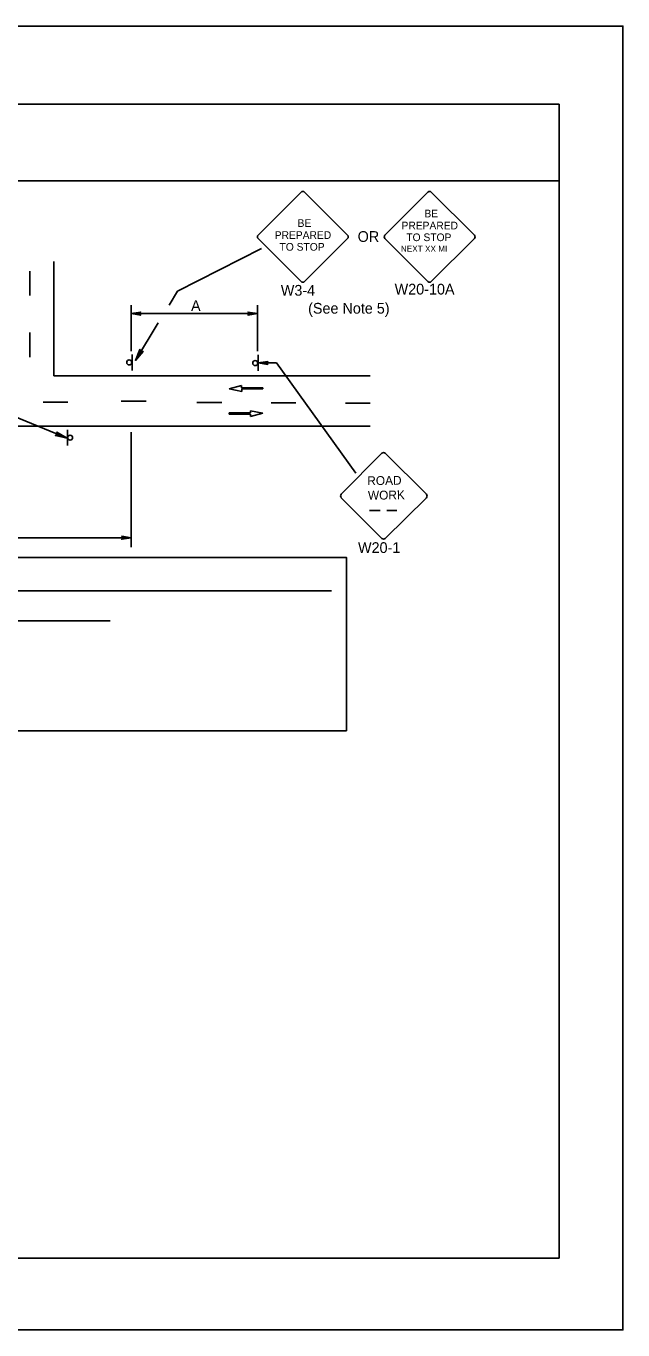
# Model space of a CAD drawing. Extents: x -14145 to -13521, y 30244 to 30661.
# Drawn here: x -13904.84 to -13893.17, y 30451.81 to 30477.31 of the extents above; entities that cross this region are included whole.
import ezdxf

# ---------------------------------------------------------------- set-up
doc = ezdxf.new("R2010")
doc.units = 0
for name, color, linetype in [('1', 7, 'Continuous'), ('10', 7, 'Continuous'), ('2', 7, 'Continuous'), ('61', 7, 'Continuous')]:
    doc.layers.add(name, color=color, linetype=linetype)

msp = doc.modelspace()

# ---------------------------------------------------------------- linework, layer by layer
at = {"layer": '1'}
for p, q in [((-13901.878, 30472.123), (-13900.236, 30472.955)), ((-13904.767, 30472.035), (-13904.767, 30472.515)), ((-13904.299, 30470.468), (-13904.299, 30472.704)), ((-13902.046, 30471.847), (-13901.878, 30472.123)), ((-13902.785, 30470.952), (-13902.785, 30471.849)), ((-13900.319, 30470.946), (-13900.319, 30471.849)), ((-13900.319, 30471.684), (-13902.785, 30471.684)), ((-13902.704, 30470.768), (-13902.257, 30471.502)), ((-13904.767, 30471.311), (-13904.767, 30470.831)), ((-13902.767, 30470.886), (-13902.767, 30470.568)), ((-13900.301, 30470.88), (-13900.301, 30470.562)), ((-13899.947, 30470.718), (-13900.301, 30470.718)), ((-13899.947, 30470.718), (-13898.393, 30468.564)), ((-13904.299, 30470.468), (-13898.113, 30470.468)), ((-13900.627, 30470.276), (-13900.868, 30470.21)), ((-13900.868, 30470.21), (-13900.624, 30470.163)), ((-13900.627, 30470.231), (-13900.627, 30470.276)), ((-13900.211, 30470.231), (-13900.627, 30470.231)), ((-13900.624, 30470.163), (-13900.624, 30470.209)), ((-13900.624, 30470.209), (-13900.211, 30470.209)), ((-13900.211, 30470.209), (-13900.211, 30470.231)), ((-13904.027, 30469.952), (-13904.507, 30469.952)), ((-13902.493, 30469.97), (-13902.979, 30469.97)), ((-13901.017, 30469.946), (-13901.503, 30469.946)), ((-13900.454, 30469.74), (-13900.868, 30469.74)), ((-13900.868, 30469.74), (-13900.868, 30469.718)), ((-13900.868, 30469.718), (-13900.452, 30469.718)), ((-13900.211, 30469.739), (-13900.454, 30469.785)), ((-13900.454, 30469.785), (-13900.454, 30469.74)), ((-13900.452, 30469.673), (-13900.211, 30469.739)), ((-13900.452, 30469.718), (-13900.452, 30469.673)), ((-13899.565, 30469.94), (-13900.051, 30469.94)), ((-13898.113, 30469.934), (-13898.599, 30469.934)), ((-13914.354, 30469.484), (-13898.113, 30469.484)), ((-13905.066, 30469.669), (-13904.04, 30469.246)), ((-13904.034, 30469.413), (-13904.034, 30469.101)), ((-13902.785, 30469.366), (-13902.785, 30467.114)), ((-13897.885, 30468.952), (-13898.68, 30468.149)), ((-13897.016, 30468.149), (-13897.819, 30468.952)), ((-13898.68, 30468.083), (-13897.885, 30467.288)), ((-13897.819, 30467.288), (-13897.016, 30468.083)), ((-13898.13, 30467.835), (-13897.919, 30467.835)), ((-13897.787, 30467.835), (-13897.594, 30467.835)), ((-13902.785, 30467.3), (-13916.927, 30467.3))]:
    msp.add_line(p, q, dxfattribs=at)
for points in [[(-13900.305, 30473.217), (-13899.464, 30474.059)], [(-13899.398, 30474.059), (-13898.556, 30473.217)], [(-13897.826, 30473.217), (-13896.985, 30474.059)], [(-13896.919, 30474.059), (-13896.077, 30473.217)], [(-13899.464, 30472.309), (-13900.305, 30473.152)], [(-13898.556, 30473.152), (-13899.398, 30472.309)], [(-13896.985, 30472.309), (-13897.826, 30473.152)], [(-13896.077, 30473.152), (-13896.919, 30472.309)], [(-13902.611, 30471.66), (-13902.617, 30471.672), (-13902.785, 30471.684), (-13902.611, 30471.66), (-13902.599, 30471.654), (-13902.785, 30471.684), (-13902.617, 30471.69), (-13902.611, 30471.702), (-13902.785, 30471.684), (-13902.599, 30471.714), (-13902.611, 30471.702)], [(-13900.493, 30471.702), (-13900.487, 30471.69), (-13900.319, 30471.684), (-13900.493, 30471.702), (-13900.505, 30471.714), (-13900.319, 30471.684), (-13900.487, 30471.672), (-13900.493, 30471.66), (-13900.319, 30471.684), (-13900.505, 30471.654), (-13900.493, 30471.66)], [(-13900.121, 30470.694), (-13900.127, 30470.706), (-13900.301, 30470.718), (-13900.121, 30470.694), (-13900.115, 30470.688), (-13900.301, 30470.718), (-13900.127, 30470.724), (-13900.121, 30470.736), (-13900.301, 30470.718), (-13900.115, 30470.748), (-13900.121, 30470.736)], [(-13902.959, 30467.318), (-13902.953, 30467.306), (-13902.785, 30467.3), (-13902.959, 30467.318), (-13902.971, 30467.33), (-13902.785, 30467.3), (-13902.953, 30467.288), (-13902.959, 30467.276), (-13902.785, 30467.3), (-13902.971, 30467.27), (-13902.959, 30467.276)]]:
    msp.add_lwpolyline(points, dxfattribs=at)
for centre, start, end in [((-13899.431, 30474.026), 45.0316, 135), ((-13896.952, 30474.026), 45.0316, 135), ((-13900.272, 30473.185), 135, 224.9684), ((-13898.589, 30473.185), 315, 45.0316), ((-13897.793, 30473.185), 135, 224.9684), ((-13896.109, 30473.185), 315, 45.0316), ((-13899.431, 30472.342), 224.9684, 315), ((-13896.952, 30472.342), 224.9684, 315), ((-13897.851, 30468.919), 45, 135), ((-13898.646, 30468.117), 135, 225), ((-13897.048, 30468.116), 315, 45), ((-13897.851, 30467.321), 225, 315)]:
    msp.add_arc(centre, 0.0465, start, end, dxfattribs=at)
at = {"layer": '10'}
for p, q in [((-13925.874, 30475.777), (-13894.422, 30475.777)), ((-13894.422, 30475.777), (-13894.422, 30453.207)), ((-13925.874, 30474.277), (-13894.422, 30474.277)), ((-13894.422, 30453.207), (-13925.874, 30453.207))]:
    msp.add_line(p, q, dxfattribs=at)
at = {"layer": '2'}
for p, q in [((-13918.818, 30466.261), (-13898.868, 30466.261)), ((-13914.632, 30465.676), (-13903.195, 30465.676))]:
    msp.add_line(p, q, dxfattribs=at)
for points in [[(-13902.567, 30470.94), (-13902.585, 30470.941), (-13902.704, 30470.768), (-13902.567, 30470.94), (-13902.553, 30470.945), (-13902.704, 30470.768), (-13902.604, 30470.953), (-13902.613, 30470.967), (-13902.704, 30470.768), (-13902.616, 30470.983), (-13902.613, 30470.967)], [(-13904.231, 30469.354), (-13904.23, 30469.336), (-13904.04, 30469.246), (-13904.231, 30469.354), (-13904.238, 30469.367), (-13904.04, 30469.246), (-13904.238, 30469.316), (-13904.251, 30469.305), (-13904.04, 30469.246), (-13904.266, 30469.299), (-13904.251, 30469.305)]]:
    msp.add_lwpolyline(points, dxfattribs=at)
msp.add_lwpolyline([(-13918.95, 30466.915), (-13898.579, 30466.915), (-13898.579, 30463.524), (-13918.95, 30463.524)], close=True, dxfattribs=at)
for centre in [(-13902.824, 30470.729), (-13900.361, 30470.717), (-13903.981, 30469.257)]:
    msp.add_circle(centre, 0.0493, dxfattribs=at)
at = {"layer": '61'}
msp.add_lwpolyline([(-13926.174, 30477.307), (-13893.174, 30477.307), (-13893.174, 30451.807), (-13926.174, 30451.807)], close=True, dxfattribs=at)

# ---------------------------------------------------------------- texts
at = {"layer": '1'}
for s, height, p in [('BE', 0.15, (-13899.533, 30473.379)), ('BE', 0.15, (-13897.054, 30473.566)), ('PREPARED', 0.15, (-13899.98, 30473.144)), ('PREPARED', 0.15, (-13897.501, 30473.331)), ('TO STOP', 0.15, (-13899.886, 30472.914)), ('NEXT XX MI', 0.12, (-13897.515, 30472.892)), ('TO STOP', 0.15, (-13897.407, 30473.101))]:
    msp.add_text(s, height=height, dxfattribs=at).set_placement(p)
for s, height, rotation, p in [('ROAD', 0.1735, 0.7566, (-13898.17, 30468.328)), ('WORK', 0.1733, 0.7588, (-13898.157, 30468.043))]:
    msp.add_text(s, height=height, rotation=rotation, dxfattribs=at).set_placement(p)
at = {"layer": '2'}
for s, p in [('OR', (-13898.359, 30473.086)), ('W3-4', (-13899.861, 30472.034)), ('W20-10A', (-13897.636, 30472.057)), ('A', (-13901.616, 30471.733)), ('(See Note 5)', (-13899.327, 30471.683)), ('W20-1', (-13898.352, 30467.002))]:
    msp.add_text(s, height=0.21, dxfattribs=at).set_placement(p)

doc.saveas('drawing.dxf')
